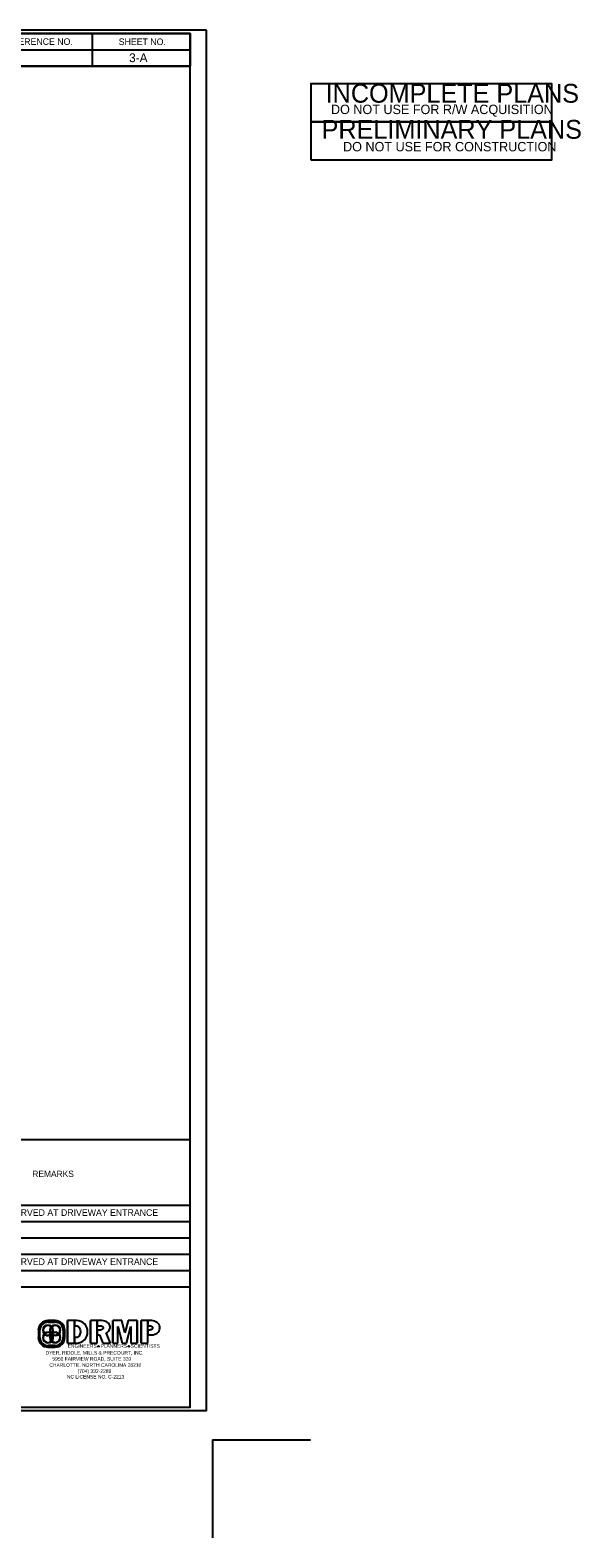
# Model space of a CAD drawing. Extents: x 573895.7 to 573936.5, y -53270.1 to -53245.1.
# Drawn here: x 573928.13 to 573936.55, y -53270.09 to -53247.04 of the extents above; entities that cross this region are included whole.
import ezdxf

# ---------------------------------------------------------------- set-up
doc = ezdxf.new("R2010")
doc.units = 0
for name, color, linetype in [('Old_Level_43', 7, 'Continuous'), ('Old_Level_51', 7, 'Continuous'), ('Sheet Data Field CELL', 7, 'Continuous'), ('Sheet Plot Border Inside CELL', 7, 'Continuous'), ('Sheet Sticker Incomplete CELL', 7, 'Continuous'), ('Sheet Sticker Preliminary CELL', 7, 'Continuous'), ('Sheet Summary Combination CELL', 7, 'Continuous'), ('Sheet Summary Combination Grid CELL', 7, 'Continuous')]:
    doc.layers.add(name, color=color, linetype=linetype)

msp = doc.modelspace()

# ---------------------------------------------------------------- linework, layer by layer
at = {"layer": 'Old_Level_51'}
for p, q in [((573928.254, -53266.92), (573928.254, -53267.03)), ((573928.278, -53267.03), (573928.278, -53266.92)), ((573928.511, -53266.772), (573928.402, -53266.772)), ((573928.402, -53266.796), (573928.511, -53266.796)), ((573928.511, -53266.796), (573928.511, -53266.772)), ((573928.511, -53266.772), (573928.511, -53266.796)), ((573928.635, -53266.92), (573928.635, -53267.03)), ((573928.66, -53267.03), (573928.66, -53266.92)), ((573928.702, -53267.115), (573928.702, -53266.772)), ((573928.808, -53266.772), (573928.702, -53266.772)), ((573928.702, -53266.772), (573928.702, -53267.115)), ((573928.808, -53266.851), (573928.808, -53266.772)), ((573928.838, -53266.772), (573928.808, -53266.772)), ((573928.808, -53266.772), (573928.808, -53266.851)), ((573928.808, -53267.032), (573928.808, -53266.851)), ((573928.808, -53266.851), (573928.837, -53266.851)), ((573928.837, -53266.851), (573928.848, -53266.852)), ((573928.848, -53266.852), (573928.858, -53266.856)), ((573928.858, -53266.856), (573928.868, -53266.863)), ((573928.868, -53266.863), (573928.876, -53266.875)), ((573928.876, -53266.875), (573928.883, -53266.887)), ((573928.883, -53266.887), (573928.89, -53266.899)), ((573928.89, -53266.899), (573928.894, -53266.915)), ((573928.894, -53266.915), (573928.896, -53266.932)), ((573928.896, -53266.932), (573928.896, -53266.948)), ((573929.052, -53267.115), (573929.052, -53266.772)), ((573929.155, -53266.772), (573929.052, -53266.772)), ((573929.052, -53266.772), (573929.052, -53267.115)), ((573929.155, -53266.851), (573929.155, -53266.772)), ((573929.224, -53266.772), (573929.155, -53266.772)), ((573929.155, -53266.772), (573929.155, -53266.851)), ((573929.155, -53266.916), (573929.155, -53266.851)), ((573929.155, -53266.851), (573929.204, -53266.851)), ((573929.155, -53266.989), (573929.155, -53266.916)), ((573929.204, -53266.916), (573929.155, -53266.916)), ((573929.155, -53266.916), (573929.155, -53266.989)), ((573929.204, -53266.851), (573929.213, -53266.851)), ((573929.213, -53266.915), (573929.204, -53266.916)), ((573929.213, -53266.851), (573929.22, -53266.852)), ((573929.22, -53266.915), (573929.213, -53266.915)), ((573929.22, -53266.852), (573929.227, -53266.854)), ((573929.227, -53266.911), (573929.22, -53266.915)), ((573929.248, -53266.773), (573929.224, -53266.772)), ((573929.227, -53266.854), (573929.232, -53266.858)), ((573929.232, -53266.906), (573929.227, -53266.911)), ((573929.232, -53266.858), (573929.237, -53266.863)), ((573929.237, -53266.903), (573929.232, -53266.906)), ((573929.237, -53266.863), (573929.242, -53266.868)), ((573929.242, -53266.898), (573929.237, -53266.903)), ((573929.242, -53266.868), (573929.244, -53266.875)), ((573929.244, -53266.892), (573929.242, -53266.898)), ((573929.244, -53266.875), (573929.245, -53266.881)), ((573929.245, -53266.887), (573929.244, -53266.892)), ((573929.245, -53266.881), (573929.245, -53266.887)), ((573929.27, -53266.778), (573929.248, -53266.773)), ((573929.291, -53266.786), (573929.27, -53266.778)), ((573929.309, -53266.798), (573929.291, -53266.786)), ((573929.325, -53266.812), (573929.309, -53266.798)), ((573929.309, -53266.946), (573929.325, -53266.933)), ((573929.339, -53266.827), (573929.325, -53266.812)), ((573929.325, -53266.933), (573929.339, -53266.917)), ((573929.345, -53266.844), (573929.339, -53266.827)), ((573929.339, -53266.917), (573929.345, -53266.899)), ((573929.35, -53266.863), (573929.345, -53266.844)), ((573929.345, -53266.899), (573929.35, -53266.882)), ((573929.35, -53266.882), (573929.35, -53266.863)), ((573929.392, -53267.115), (573929.392, -53266.772)), ((573929.53, -53266.772), (573929.392, -53266.772)), ((573929.392, -53266.772), (573929.392, -53267.115)), ((573929.47, -53267.115), (573929.47, -53266.861)), ((573929.47, -53266.861), (573929.535, -53267.115)), ((573929.577, -53266.959), (573929.53, -53266.772)), ((573929.626, -53266.772), (573929.577, -53266.959)), ((573929.601, -53267.115), (573929.667, -53266.861)), ((573929.763, -53266.772), (573929.626, -53266.772)), ((573929.667, -53266.861), (573929.667, -53267.115)), ((573929.763, -53266.772), (573929.763, -53267.115)), ((573929.763, -53267.115), (573929.763, -53266.772)), ((573929.824, -53267.115), (573929.824, -53266.772)), ((573929.928, -53266.772), (573929.824, -53266.772)), ((573929.824, -53266.772), (573929.824, -53267.115)), ((573929.928, -53266.851), (573929.928, -53266.772)), ((573929.987, -53266.772), (573929.928, -53266.772)), ((573929.928, -53266.772), (573929.928, -53266.851)), ((573929.928, -53266.916), (573929.928, -53266.851)), ((573929.928, -53266.851), (573929.96, -53266.851)), ((573929.928, -53266.989), (573929.928, -53266.916)), ((573929.96, -53266.916), (573929.928, -53266.916)), ((573929.928, -53266.916), (573929.928, -53266.989)), ((573929.96, -53266.851), (573929.967, -53266.851)), ((573929.967, -53266.915), (573929.96, -53266.916)), ((573929.967, -53266.851), (573929.973, -53266.852)), ((573929.973, -53266.915), (573929.967, -53266.915)), ((573929.973, -53266.852), (573929.981, -53266.854)), ((573929.981, -53266.911), (573929.973, -53266.915)), ((573929.981, -53266.854), (573929.987, -53266.858)), ((573929.987, -53266.906), (573929.981, -53266.911)), ((573930.009, -53266.773), (573929.987, -53266.772)), ((573929.987, -53266.858), (573929.993, -53266.863)), ((573929.993, -53266.903), (573929.987, -53266.906)), ((573929.993, -53266.863), (573929.995, -53266.868)), ((573929.995, -53266.898), (573929.993, -53266.903)), ((573929.995, -53266.868), (573929.998, -53266.875)), ((573929.998, -53266.892), (573929.995, -53266.898)), ((573929.998, -53266.875), (573930, -53266.881)), ((573930, -53266.887), (573929.998, -53266.892)), ((573930, -53266.881), (573930, -53266.887)), ((573930.033, -53266.779), (573930.009, -53266.773)), ((573930.051, -53266.788), (573930.033, -53266.779)), ((573930.072, -53266.801), (573930.051, -53266.788)), ((573930.087, -53266.815), (573930.072, -53266.801)), ((573930.099, -53266.832), (573930.087, -53266.815)), ((573930.087, -53266.946), (573930.099, -53266.929)), ((573930.108, -53266.852), (573930.099, -53266.832)), ((573930.099, -53266.929), (573930.108, -53266.909)), ((573930.113, -53266.869), (573930.108, -53266.852)), ((573930.108, -53266.909), (573930.113, -53266.891)), ((573930.113, -53266.891), (573930.113, -53266.869)), ((573928.402, -53267.154), (573928.402, -53267.178)), ((573928.402, -53267.178), (573928.402, -53267.154)), ((573928.511, -53267.154), (573928.402, -53267.154)), ((573928.402, -53267.154), (573928.402, -53267.178)), ((573928.702, -53267.115), (573928.808, -53267.115)), ((573928.808, -53267.115), (573928.808, -53267.032)), ((573928.837, -53267.032), (573928.808, -53267.032)), ((573928.808, -53267.032), (573928.808, -53267.115)), ((573928.808, -53267.115), (573928.838, -53267.115)), ((573928.848, -53267.03), (573928.837, -53267.032)), ((573928.858, -53267.025), (573928.848, -53267.03)), ((573928.868, -53267.018), (573928.858, -53267.025)), ((573928.876, -53267.008), (573928.868, -53267.018)), ((573928.883, -53266.995), (573928.876, -53267.008)), ((573928.89, -53266.981), (573928.883, -53266.995)), ((573928.894, -53266.965), (573928.89, -53266.981)), ((573928.896, -53266.948), (573928.894, -53266.965)), ((573929.052, -53267.115), (573929.155, -53267.115)), ((573929.155, -53267.115), (573929.155, -53266.989)), ((573929.155, -53266.989), (573929.188, -53266.989)), ((573929.188, -53266.989), (573929.241, -53267.115)), ((573929.241, -53267.115), (573929.355, -53267.115)), ((573929.291, -53266.959), (573929.309, -53266.946)), ((573929.355, -53267.115), (573929.291, -53266.959)), ((573929.392, -53267.115), (573929.47, -53267.115)), ((573929.535, -53267.115), (573929.601, -53267.115)), ((573929.667, -53267.115), (573929.763, -53267.115)), ((573929.824, -53267.115), (573929.928, -53267.115)), ((573929.928, -53267.115), (573929.928, -53266.989)), ((573929.928, -53266.989), (573929.987, -53266.989)), ((573929.987, -53266.989), (573930.009, -53266.987)), ((573930.009, -53266.987), (573930.033, -53266.981)), ((573930.033, -53266.981), (573930.051, -53266.973)), ((573930.051, -53266.973), (573930.072, -53266.961)), ((573930.072, -53266.961), (573930.087, -53266.946)), ((573928.402, -53267.178), (573928.511, -53267.178))]:
    msp.add_line(p, q, dxfattribs=at)
for centre, radius, start, end in [((573928.401, -53266.92), 0.148, 89.8427, 180.041), ((573928.401, -53266.92), 0.124, 89.8427, 180.041), ((573928.401, -53266.92), 0.0805, 46.7635, 222.824), ((573928.401, -53266.919), 0.0745, 46.6636, 222.9363), ((573928.511, -53266.92), 0.0805, 136.9868, 222.9133), ((573928.511, -53266.92), 0.0744, 137.2813, 222.834), ((573928.511, -53266.92), 0.0805, 132.9319, 136.9868), ((573928.511, -53266.92), 0.0805, 132.9319, 136.9868), ((573928.401, -53266.919), 0.0745, 42.0715, 46.6636), ((573928.401, -53266.919), 0.0745, 42.0715, 46.6636), ((573928.401, -53266.919), 0.0745, 316.7514, 42.0715), ((573928.511, -53266.92), 0.0805, 317.2439, 132.9319), ((573928.401, -53266.92), 0.0805, 42.5237, 46.7635), ((573928.401, -53266.92), 0.0805, 42.5237, 46.7635), ((573928.511, -53266.92), 0.0744, 132.8738, 137.2813), ((573928.511, -53266.92), 0.0744, 132.8738, 137.2813), ((573928.511, -53266.92), 0.0744, 0, 132.8738), ((573928.401, -53266.92), 0.0805, 316.8625, 42.5237), ((573928.511, -53266.92), 0.148, 359.959, 89.9237), ((573928.511, -53266.92), 0.124, 0.0047, 89.9943), ((573928.511, -53266.92), 0.0744, 317.3272, 359.997), ((573928.835, -53266.943), 0.172, 270.9756, 89.0245), ((573928.835, -53266.943), 0.172, 0, 89.0245), ((573928.401, -53267.029), 0.148, 180.041, 269.9576), ((573928.401, -53267.029), 0.124, 180.0792, 269.9193), ((573928.401, -53267.03), 0.0806, 136.7479, 313.2075), ((573928.401, -53267.03), 0.0746, 136.7341, 313.2615), ((573928.401, -53267.03), 0.0806, 132.2482, 136.7479), ((573928.401, -53267.03), 0.0806, 132.2482, 136.7479), ((573928.401, -53266.92), 0.0805, 222.824, 226.9567), ((573928.401, -53266.92), 0.0805, 222.8234, 239.9965), ((573928.401, -53267.03), 0.0806, 46.7925, 132.2482), ((573928.401, -53266.919), 0.0745, 222.9363, 227.4213), ((573928.401, -53266.919), 0.0745, 222.9354, 311.9542), ((573928.401, -53267.03), 0.0746, 46.7386, 131.8484), ((573928.401, -53266.92), 0.0805, 240, 312.4163), ((573928.511, -53267.03), 0.0806, 137.1377, 222.3661), ((573928.512, -53267.03), 0.0746, 137.4623, 221.9341), ((573928.401, -53267.03), 0.0746, 42.6389, 47.5271), ((573928.401, -53266.919), 0.0745, 312.5526, 317.3015), ((573928.511, -53267.03), 0.0806, 133.2075, 137.6339), ((573928.511, -53267.03), 0.0806, 133.2075, 137.1377), ((573928.511, -53266.92), 0.0805, 222.2294, 227.36), ((573928.511, -53266.92), 0.0805, 222.9133, 227.3599), ((573928.401, -53267.03), 0.0746, 313.2615, 318.0659), ((573928.401, -53267.03), 0.0746, 313.2614, 318.0658), ((573928.511, -53267.03), 0.0806, 222.3661, 226.7925), ((573928.511, -53267.03), 0.0806, 222.3661, 226.7917), ((573928.401, -53267.03), 0.0806, 42.9386, 47.4396), ((573928.401, -53267.03), 0.0746, 0, 42.6399), ((573928.511, -53266.92), 0.0744, 222.0917, 227.6268), ((573928.401, -53266.92), 0.0805, 312.923, 317.3196), ((573928.511, -53267.03), 0.0806, 226.7925, 43.0195), ((573928.511, -53266.92), 0.0805, 226.7546, 313.1115), ((573928.511, -53266.92), 0.0805, 226.7546, 240.0366), ((573928.401, -53267.03), 0.0746, 318.0659, 359.997), ((573928.512, -53267.03), 0.0746, 221.9341, 226.7386), ((573928.512, -53267.03), 0.0746, 221.9341, 226.7385), ((573928.401, -53267.03), 0.0806, 313.2075, 317.6339), ((573928.401, -53267.03), 0.0806, 313.2075, 317.6339), ((573928.512, -53267.03), 0.0746, 132.7168, 137.4623), ((573928.512, -53267.03), 0.0746, 47.7542, 133.2488), ((573928.401, -53266.92), 0.0805, 316.8625, 330.1026), ((573928.511, -53266.92), 0.0744, 226.9694, 312.8439), ((573928.401, -53267.03), 0.0806, 317.6339, 29.6767), ((573928.512, -53267.03), 0.0746, 226.7386, 359.997), ((573928.511, -53267.03), 0.0806, 47.4033, 120), ((573928.511, -53267.03), 0.124, 269.8659, 0.1326), ((573928.511, -53267.029), 0.148, 270.041, 359.959), ((573928.511, -53266.92), 0.0744, 312.8441, 317.3272), ((573928.511, -53266.92), 0.0744, 312.8441, 317.3272), ((573928.512, -53267.03), 0.0746, 43.0093, 47.7542), ((573928.512, -53267.03), 0.0746, 43.0093, 47.7542), ((573928.511, -53267.03), 0.0806, 43.0195, 47.4033), ((573928.511, -53267.03), 0.0806, 43.0195, 47.4033), ((573928.511, -53266.92), 0.0805, 313.1116, 317.2439), ((573928.511, -53266.92), 0.0805, 313.1116, 317.2439), ((573928.512, -53267.03), 0.0746, 0, 43.0093), ((573928.835, -53266.943), 0.172, 270.9756, 359.9986)]:
    msp.add_arc(centre, radius, start, end, dxfattribs=at)
for centre in [(573929.172, -53267.167), (573929.639, -53267.167)]:
    msp.add_ellipse(centre, major_axis=(0, -0.0082), ratio=0.834135, dxfattribs=at)
at = {"layer": 'Sheet Plot Border Inside CELL'}
msp.add_lwpolyline([(573930.827, -53247.042), (573897.497, -53247.042), (573897.497, -53268.144), (573930.827, -53268.144)], close=True, dxfattribs=at)
at = {"layer": 'Sheet Sticker Incomplete CELL'}
msp.add_lwpolyline([(573932.423, -53248.444), (573932.423, -53247.856), (573936.098, -53247.856), (573936.098, -53248.444)], close=True, dxfattribs=at)
at = {"layer": 'Sheet Sticker Preliminary CELL'}
msp.add_lwpolyline([(573932.423, -53249.031), (573932.423, -53248.444), (573936.098, -53248.444), (573936.098, -53249.031)], close=True, dxfattribs=at)
at = {"layer": 'Sheet Summary Combination CELL'}
for p, q in [((573929.077, -53247.094), (573929.077, -53247.594)), ((573926.576, -53247.344), (573930.577, -53247.344)), ((573926.576, -53247.594), (573930.577, -53247.594)), ((573930.917, -53268.593), (573932.417, -53268.593)), ((573930.917, -53268.593), (573930.917, -53270.093))]:
    msp.add_line(p, q, dxfattribs=at)
for points in [[(573930.577, -53247.093), (573900.577, -53247.093), (573900.577, -53268.093), (573930.577, -53268.093)], [(573926.576, -53247.093), (573930.577, -53247.093), (573930.577, -53247.594), (573926.576, -53247.594)]]:
    msp.add_lwpolyline(points, close=True, dxfattribs=at)
at = {"layer": 'Sheet Summary Combination Grid CELL'}
for p, q in [((573900.577, -53264.004), (573930.577, -53264.004)), ((573900.577, -53265.004), (573930.577, -53265.004)), ((573900.577, -53265.254), (573930.577, -53265.254)), ((573900.577, -53265.504), (573930.577, -53265.504)), ((573900.577, -53265.754), (573930.577, -53265.754)), ((573900.577, -53266.004), (573930.577, -53266.004)), ((573900.577, -53266.254), (573930.577, -53266.254))]:
    msp.add_line(p, q, dxfattribs=at)

# ---------------------------------------------------------------- texts
at = {"layer": 'Old_Level_43'}
for s, p in [('DYER, RIDDLE, MILLS & PRECOURT, INC.', (573928.364, -53267.291)), ('5950 FAIRVIEW ROAD, SUITE 320', (573928.468, -53267.384)), ('CHARLOTTE, NORTH CAROLINA 28210', (573928.422, -53267.478))]:
    msp.add_text(s, height=0.05472, dxfattribs=at).set_placement(p)
for s, p in [('NC LICENSE NO. C-2213', (573928.69, -53267.657)), ('(704) 332-2289', (573928.853, -53267.571))]:
    msp.add_text(s, height=0.05472, rotation=360, dxfattribs=at).set_placement(p)
at = {"layer": 'Old_Level_51'}
for s, p in [('ENGINEERS', (573928.702, -53267.187)), ('PLANNERS', (573929.204, -53267.187)), ('SCIENTISTS', (573929.667, -53267.187))]:
    msp.add_text(s, height=0.0547, dxfattribs=at).set_placement(p)
at = {"layer": 'Sheet Data Field CELL'}
msp.add_text('3-A', height=0.135, dxfattribs=at).set_placement((573929.642, -53247.531))
at = {"layer": 'Sheet Sticker Incomplete CELL'}
for s, height, p in [('INCOMPLETE PLANS', 0.288, (573932.647, -53248.151)), ('DO NOT USE FOR R/W ACQUISITION', 0.144, (573932.728, -53248.325))]:
    msp.add_text(s, height=height, rotation=360, dxfattribs=at).set_placement(p)
at = {"layer": 'Sheet Sticker Preliminary CELL'}
for s, height, p in [('PRELIMINARY PLANS', 0.288, (573932.585, -53248.702)), ('DO NOT USE FOR CONSTRUCTION', 0.144, (573932.913, -53248.895))]:
    msp.add_text(s, height=height, rotation=360, dxfattribs=at).set_placement(p)
at = {"layer": 'Sheet Summary Combination CELL'}
for s, height, p in [('PROJECT REFERENCE NO.', 0.1, (573927.02, -53247.267)), ('SHEET NO.', 0.1, (573929.483, -53247.269)), ('REMARKS', 0.096, (573928.162, -53264.576)), ('SHOP CURVED AT DRIVEWAY ENTRANCE', 0.1, (573927.374, -53265.17)), ('SHOP CURVED AT DRIVEWAY ENTRANCE', 0.1, (573927.374, -53265.92))]:
    msp.add_text(s, height=height, dxfattribs=at).set_placement(p)

doc.saveas('drawing.dxf')
